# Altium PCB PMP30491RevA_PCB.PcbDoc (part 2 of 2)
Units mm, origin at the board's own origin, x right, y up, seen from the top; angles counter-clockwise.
Board outline 40.64 x 55.88 mm, 4 copper layers (Top Layer, Layer 2, Layer 3, Bottom Layer), stack 2.028 mm thick; 56 components, 28 nets, 145 pads, 91 vias.
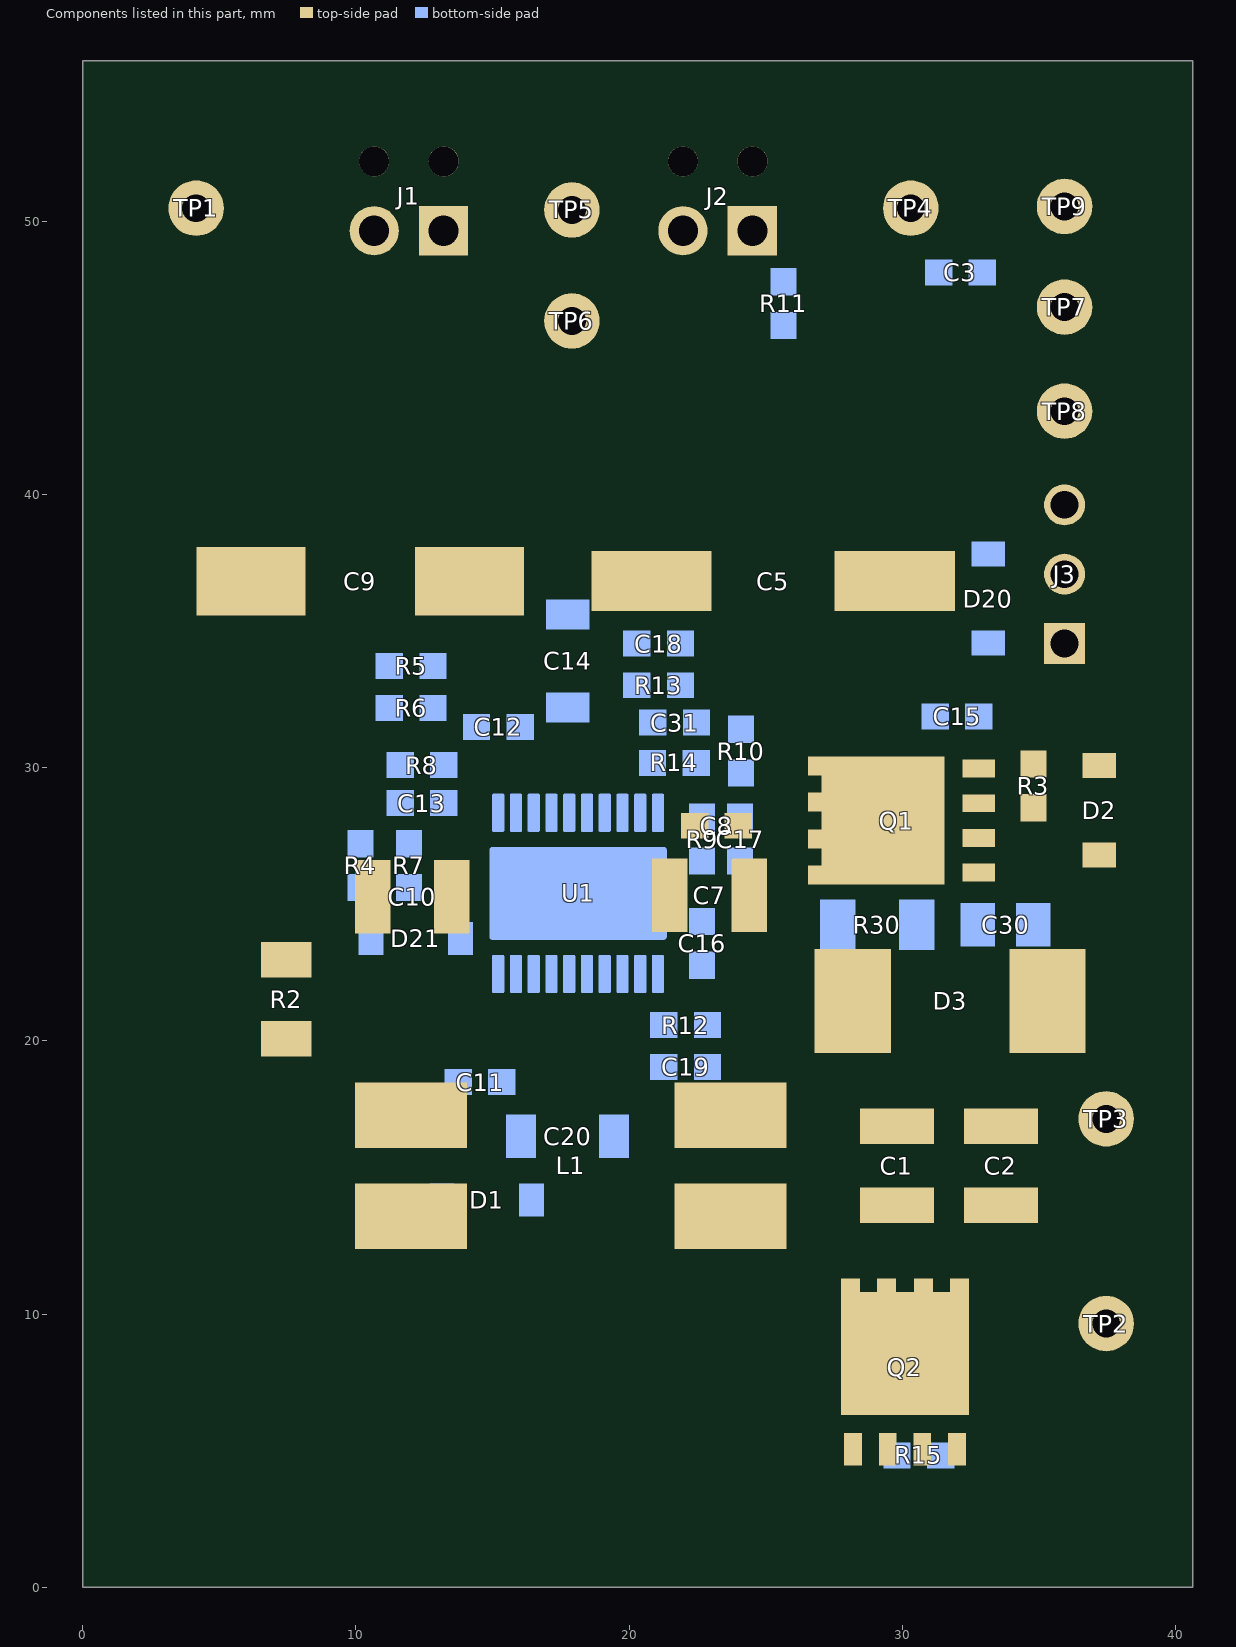
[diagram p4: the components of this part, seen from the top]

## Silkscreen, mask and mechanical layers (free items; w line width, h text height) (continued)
Drill Drawing:
  lines w0.254: 134.268,67.2 135.674,67.2 134.971,65.795 134.268,67.2 ; 134.268,68.957 135.674,68.957 135.674,70.363 134.268,70.363 134.268,68.957 ; 134.268,72.471 134.62,72.471 134.62,72.119 135.323,72.119 135.323,72.471 135.674,72.471 135.674,73.174 135.323,73.174 135.323,73.525 134.62,73.525 134.62,73.174 134.268,73.174 134.268,72.471 ; 134.268,75.282 134.268,75.633 134.62,75.985 134.268,76.336 134.268,76.687 134.62,76.687 134.971,76.336 135.323,76.687 135.674,76.687 135.674,76.336 135.323,75.985 135.674,75.633 135.674,75.282 135.323,75.282 134.971,75.633 134.62,75.282 134.268,75.282 ; 134.268,78.795 134.62,78.795 134.971,78.444 135.323,78.795 135.674,78.795 135.323,79.147 135.674,79.498 135.323,79.498 134.971,79.85 134.62,79.498 134.268,79.498 134.62,79.147 134.268,78.795
  lines w0.305: 132.994,64.846 211.175,64.846 ; 132.994,80.658 211.175,80.658 ; 141.58,61.684 141.58,83.82 ; 150.017,61.684 150.017,83.82 ; 166.183,61.684 166.183,83.82 ; 172.767,61.684 172.767,83.82 ; 182.298,61.684 182.298,83.82 ; 200.702,61.684 200.702,83.82 ; 132.994,61.684 211.175,61.684 211.175,83.82 132.994,83.82 132.994,61.684
  text "Symbol" at 134.892,81.606 h1.83
  text "Quantity" at 142.529,81.606 h1.83
  text "Finished Hole Size" at 150.965,81.606 h1.83
  text "Plated" at 167.132,81.606 h1.83
  text "Hole Type" at 173.716,81.606 h1.83
  text "Drill Layer Pair" at 183.247,81.606 h1.83
  text "Tolerance" at 201.65,81.606 h1.83
  text "4" at 142.529,78.444 h1.52
  text "43.31mil (1.100mm)" at 150.965,78.444 h1.52
  text "NPTH" at 167.132,78.444 h1.52
  text "Round" at 173.716,78.444 h1.52
  text "Top Layer - Bottom Layer" at 183.247,78.444 h1.52
  text "49" at 142.529,75.282 h1.52
  text "11.81mil (0.300mm)" at 150.965,75.282 h1.52
  text "PTH" at 167.132,75.282 h1.52
  text "Round" at 173.716,75.282 h1.52
  text "Top Layer - Bottom Layer" at 183.247,75.282 h1.52
  text "42" at 142.529,72.119 h1.52
  text "19.69mil (0.500mm)" at 150.965,72.119 h1.52
  text "PTH" at 167.132,72.119 h1.52
  text "Round" at 173.716,72.119 h1.52
  text "Top Layer - Bottom Layer" at 183.247,72.119 h1.52
  text "12" at 142.529,68.957 h1.52
  text "40.00mil (1.016mm)" at 150.965,68.957 h1.52
  text "PTH" at 167.132,68.957 h1.52
  text "Round" at 173.716,68.957 h1.52
  text "Top Layer - Bottom Layer" at 183.247,68.957 h1.52
  text "4" at 142.529,65.795 h1.52
  text "43.31mil (1.100mm)" at 150.965,65.795 h1.52
  text "PTH" at 167.132,65.795 h1.52
  text "Round" at 173.716,65.795 h1.52
  text "Top Layer - Bottom Layer" at 183.247,65.795 h1.52
  text "111 Total" at 142.529,62.633 h1.52
  text ".Layer_Name" at 13.386,-25.616 h1.52

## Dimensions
3.302,2.286 to 3.302,42.926 on Top Overlay
3.302,43.18 to 38.354,42.926 on Top Overlay
0,55.88 to 0,0 on M2 Board Dimensions
0,0 to 40.64,-0.254 on M2 Board Dimensions
-1.27,-13.97 to 24.13,-13.97 on M2 Board Dimensions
